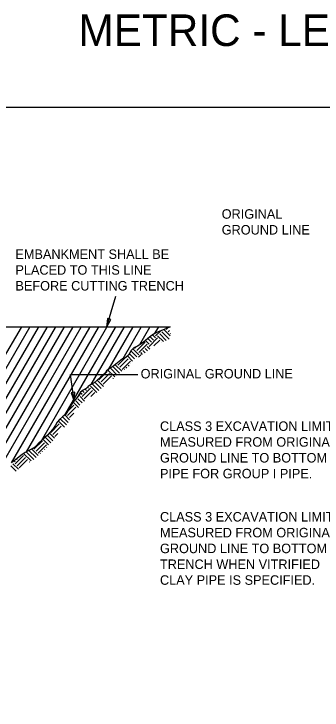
# Model space of a CAD drawing. Extents: x -439.1 to -407.9, y -458.1 to -436.2.
# Drawn here: x -430.66 to -425.79, y -447.2 to -436.2 of the extents above; entities that cross this region are included whole.
import ezdxf

# ---------------------------------------------------------------- set-up
doc = ezdxf.new("R2010")
doc.units = 0
for name, color, linetype in [('Bridge-Named Boundary', 7, 'Continuous'), ('Level 4', 7, 'Continuous'), ('Level 46', 7, 'Continuous')]:
    doc.layers.add(name, color=color, linetype=linetype)

msp = doc.modelspace()

# ---------------------------------------------------------------- linework, layer by layer
at = {"layer": 'Bridge-Named Boundary'}
msp.add_lwpolyline([(-439.109, -458.051), (-407.859, -458.051), (-407.859, -437.676), (-439.109, -437.676)], close=True, dxfattribs=at)
at = {"layer": 'Level 4'}
for p, q in [((-429.197, -441.152), (-429.054, -440.659)), ((-438.443, -441.15), (-428.195, -441.145)), ((-430.55, -441.152), (-430.869, -441.704)), ((-430.279, -441.152), (-430.869, -442.173)), ((-430.144, -441.152), (-430.869, -442.407)), ((-430.009, -441.152), (-430.869, -442.642)), ((-429.874, -441.152), (-430.869, -442.876)), ((-429.738, -441.152), (-430.869, -443.11)), ((-429.603, -441.152), (-430.869, -443.345)), ((-430.415, -441.152), (-430.869, -441.939)), ((-429.468, -441.152), (-430.705, -443.295)), ((-429.332, -441.152), (-430.469, -443.12)), ((-429.197, -441.152), (-430.235, -442.949)), ((-429.062, -441.152), (-429.864, -442.54)), ((-428.926, -441.152), (-429.449, -442.057)), ((-428.791, -441.152), (-429.181, -441.827)), ((-428.656, -441.152), (-428.944, -441.65)), ((-428.52, -441.152), (-428.679, -441.426)), ((-428.385, -441.152), (-428.445, -441.255)), ((-428.424, -441.287), (-428.348, -441.211)), ((-428.192, -441.288), (-428.292, -441.188)), ((-428.25, -441.152), (-428.263, -441.174)), ((-428.258, -441.188), (-428.231, -441.161)), ((-428.225, -441.221), (-428.206, -441.202)), ((-428.524, -441.453), (-428.391, -441.32)), ((-428.457, -441.353), (-428.509, -441.302)), ((-428.424, -441.32), (-428.472, -441.273)), ((-428.3, -441.378), (-428.391, -441.287)), ((-428.254, -441.358), (-428.358, -441.254)), ((-428.207, -441.338), (-428.325, -441.221)), ((-428.192, -441.254), (-428.189, -441.251)), ((-428.722, -441.519), (-428.59, -441.387)), ((-428.689, -441.552), (-428.557, -441.42)), ((-428.524, -441.42), (-428.583, -441.361)), ((-428.49, -441.387), (-428.546, -441.331)), ((-428.449, -441.445), (-428.358, -441.353)), ((-428.327, -441.389), (-428.325, -441.387)), ((-428.722, -441.619), (-428.816, -441.525)), ((-428.689, -441.585), (-428.783, -441.492)), ((-428.756, -441.486), (-428.725, -441.455)), ((-428.589, -441.553), (-428.623, -441.519)), ((-428.552, -441.524), (-428.59, -441.486)), ((-428.515, -441.495), (-428.557, -441.453)), ((-429.021, -441.751), (-428.888, -441.619)), ((-428.988, -441.784), (-428.855, -441.652)), ((-428.789, -441.685), (-428.869, -441.605)), ((-428.756, -441.652), (-428.838, -441.569)), ((-428.696, -441.625), (-428.656, -441.585)), ((-428.629, -441.58), (-428.656, -441.552)), ((-428.958, -441.847), (-429.061, -441.744)), ((-428.954, -441.817), (-428.822, -441.685)), ((-428.842, -441.764), (-428.855, -441.751)), ((-428.819, -441.72), (-428.822, -441.718)), ((-429.319, -441.983), (-429.187, -441.851)), ((-429.067, -441.937), (-429.177, -441.827)), ((-429.031, -441.906), (-429.138, -441.8)), ((-428.996, -441.875), (-429.098, -441.773)), ((-428.917, -441.821), (-428.921, -441.817)), ((-428.876, -441.796), (-428.888, -441.784)), ((-429.709, -442.317), (-429.771, -441.898)), ((-429.771, -441.898), (-428.702, -441.898)), ((-429.286, -442.016), (-429.153, -441.884)), ((-429.253, -442.049), (-429.12, -441.917)), ((-429.096, -441.959), (-429.087, -441.95)), ((-429.353, -442.181), (-429.452, -442.083)), ((-429.32, -442.148), (-429.419, -442.049)), ((-429.285, -442.117), (-429.383, -442.018)), ((-429.249, -442.086), (-429.348, -441.988)), ((-429.584, -442.215), (-429.614, -442.186)), ((-429.584, -442.248), (-429.452, -442.116)), ((-429.551, -442.182), (-429.578, -442.155)), ((-429.551, -442.281), (-429.419, -442.149)), ((-429.518, -442.149), (-429.539, -442.128)), ((-429.485, -442.116), (-429.501, -442.099)), ((-429.446, -442.243), (-429.385, -442.182)), ((-429.658, -442.255), (-429.617, -442.215)), ((-429.585, -442.347), (-429.651, -442.281)), ((-429.546, -442.32), (-429.617, -442.248)), ((-429.816, -442.547), (-429.684, -442.414)), ((-429.807, -442.471), (-429.717, -442.381)), ((-429.75, -442.381), (-429.754, -442.377)), ((-429.644, -442.42), (-429.717, -442.348)), ((-429.619, -442.38), (-429.684, -442.315)), ((-429.783, -442.58), (-429.715, -442.511)), ((-429.865, -442.73), (-429.961, -442.634)), ((-429.833, -442.695), (-429.932, -442.597)), ((-429.806, -442.657), (-429.896, -442.567)), ((-429.783, -442.613), (-429.859, -442.537)), ((-430.081, -442.812), (-429.949, -442.679)), ((-430.048, -442.845), (-429.916, -442.712)), ((-430.049, -442.944), (-430.136, -442.857)), ((-430.02, -442.906), (-430.103, -442.824)), ((-430.015, -442.878), (-429.968, -442.831)), ((-430.347, -443.077), (-430.214, -442.944)), ((-430.115, -443.011), (-430.204, -442.921)), ((-430.081, -442.978), (-430.169, -442.89)), ((-430.28, -443.176), (-430.383, -443.073)), ((-430.313, -443.11), (-430.181, -442.978)), ((-430.28, -443.143), (-430.148, -443.011)), ((-430.175, -443.083), (-430.181, -443.077)), ((-430.142, -443.05), (-430.148, -443.044)), ((-430.645, -443.309), (-430.512, -443.176)), ((-430.545, -443.176), (-430.548, -443.174)), ((-430.391, -443.265), (-430.51, -443.146)), ((-430.348, -443.241), (-430.469, -443.12)), ((-430.313, -443.21), (-430.426, -443.097)), ((-430.245, -443.145), (-430.247, -443.143)), ((-430.21, -443.114), (-430.214, -443.11)), ((-430.645, -443.276), (-430.66, -443.261)), ((-430.612, -443.243), (-430.623, -443.231)), ((-430.612, -443.342), (-430.479, -443.21)), ((-430.579, -443.21), (-430.586, -443.202)), ((-430.579, -443.375), (-430.446, -443.243)), ((-430.417, -443.279), (-430.413, -443.276)), ((-430.63, -443.424), (-430.711, -443.342)), ((-430.593, -443.394), (-430.678, -443.309))]:
    msp.add_line(p, q, dxfattribs=at)
for points in [[(-429.186, -441.011), (-429.197, -441.152), (-429.131, -441.027)], [(-429.758, -442.185), (-429.709, -442.317), (-429.701, -442.176)]]:
    msp.add_lwpolyline(points, close=True, dxfattribs=at)
msp.add_lwpolyline([(-428.195, -441.145), (-428.263, -441.174), (-428.33, -441.203), (-428.394, -441.229), (-428.456, -441.26), (-428.52, -441.307), (-428.581, -441.359), (-428.643, -441.407), (-428.712, -441.448), (-428.766, -441.477), (-428.811, -441.516), (-428.831, -441.556), (-428.853, -441.594), (-428.896, -441.627), (-428.947, -441.652), (-429.026, -441.714), (-429.103, -441.777), (-429.153, -441.805), (-429.197, -441.84), (-429.21, -441.858), (-429.223, -441.876), (-429.258, -441.909), (-429.296, -441.939), (-429.345, -441.986), (-429.396, -442.028), (-429.424, -442.043), (-429.453, -442.059), (-429.487, -442.087), (-429.521, -442.117), (-429.567, -442.146), (-429.61, -442.179), (-429.637, -442.22), (-429.662, -442.263), (-429.698, -442.305), (-429.735, -442.346), (-429.788, -442.437), (-429.845, -442.524), (-429.894, -442.565), (-429.944, -442.607), (-429.977, -442.652), (-430.007, -442.701), (-430.048, -442.761), (-430.095, -442.816), (-430.133, -442.856), (-430.174, -442.895), (-430.221, -442.936), (-430.268, -442.978), (-430.301, -443.013), (-430.335, -443.046), (-430.371, -443.069), (-430.409, -443.088), (-430.448, -443.108), (-430.487, -443.13), (-430.535, -443.162), (-430.581, -443.197), (-430.632, -443.24), (-430.685, -443.281)], dxfattribs=at)

# ---------------------------------------------------------------- texts
for s, p in [('ORIGINAL ', (-427.378, -439.435)), ('GROUND LINE', (-427.378, -439.685)), ('EMBANKMENT SHALL BE ', (-430.639, -440.07)), ('PLACED TO THIS LINE ', (-430.639, -440.32)), ('BEFORE CUTTING TRENCH', (-430.639, -440.57)), ('ORIGINAL GROUND LINE', (-428.66, -441.96)), ('CLASS 3 EXCAVATION LIMITS', (-428.354, -442.789)), ('MEASURED FROM ORIGINAL ', (-428.354, -443.039)), ('GROUND LINE TO BOTTOM OF', (-428.354, -443.289)), ('PIPE FOR GROUP I PIPE.', (-428.354, -443.539)), ('CLASS 3 EXCAVATION LIMITS', (-428.354, -444.222)), ('MEASURED FROM ORIGINAL ', (-428.354, -444.472)), ('GROUND LINE TO BOTTOM OF ', (-428.354, -444.722)), ('TRENCH WHEN VITRIFIED ', (-428.354, -444.972)), ('CLAY PIPE IS SPECIFIED.', (-428.354, -445.222))]:
    msp.add_text(s, height=0.15, dxfattribs=at).set_placement(p)
at = {"layer": 'Level 46'}
msp.add_text('METRIC - LEVEL 46 - GREEN', height=0.5, dxfattribs=at).set_placement((-429.642, -436.705))

doc.saveas('drawing.dxf')
